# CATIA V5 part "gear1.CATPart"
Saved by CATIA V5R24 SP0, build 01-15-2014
Part number: gear1
Bounding box of the stored display mesh (mm): x -24 to 24, y -23.825 to 23.825, z -10 to 10
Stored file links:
  G:\내 드라이브\04_WORK\00_LECTURE\CAD2020\exam\gear1.CATPart
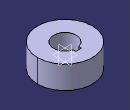
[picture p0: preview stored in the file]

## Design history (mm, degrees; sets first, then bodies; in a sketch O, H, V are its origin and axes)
Body1 (main body)
  Sketch1 on xy-plane, origin (0, 0, 0), H (1, 0, 0), V (0, 1, 0)
    arc A1 centre (0, 0) radius 10 from (-2.5, 9.6825) to (2.5, 9.6825) ccw
    circle A2 centre (0, 0) radius 24
    point P1 (0, 6.9259)
    line L1 (2.5, 12) -> (2.5, 9.6825)
    line L2 (-2.5, 9.6825) -> (-2.5, 12)
    line L3 (-2.5, 12) -> (2.5, 12)
    radius A1 = 10
    radius A2 = 24
    distance L1 L2 = 5
    distance H L3 = 12
    coincidence: P1 V
    vertical: L1 V, L2 V
    horizontal: L3 H
    equidistance: L1 L2 P1
  Pad1: profile Sketch1, direction (0, 0, 1), length 10, mirrored extent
